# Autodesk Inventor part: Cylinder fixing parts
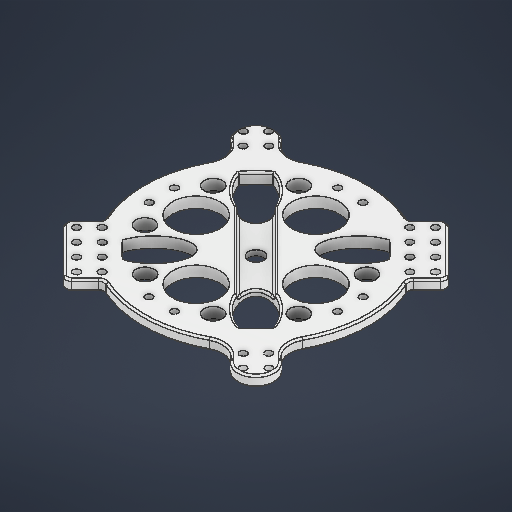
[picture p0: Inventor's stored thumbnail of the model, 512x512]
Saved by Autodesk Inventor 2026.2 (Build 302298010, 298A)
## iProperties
Created: 2026-05
Part Number: Cylinder fixing parts
Material: ABS 플라스틱
Document SubType Name: Modeling
Designer: work
Density: 1.06 g/cm^3
Appearance: 매끄러움 - 흰색
Author: work
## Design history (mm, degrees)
sketch "스케치1"
  geometry: L1 (-15, 60)-(15, 60); L2 (15, 60)-(15, -60); L3 (15, -60)-(-15, -60); L4 (-15, -60)-(-15, 60); L5 (-15, 60)-(15, -60); L6 (15, 60)-(-15, -60); L7 (-7, 52)-(7, 52); L8 (7, 52)-(7, -52); L9 (7, -52)-(-7, -52); L10 (-7, -52)-(-7, 52); L11 (-7, 52)-(7, -52); L12 (7, 52)-(-7, -52); L13 (31, -10)-(0, -10); L14 (0, -10)-(0, 10); L15 (0, 10)-(31, 10); L16 (31, 10)-(31, -10); L17 (25, 5)-(25, -5); L18 (31, 0)-(0, 0); L19 (25, 5)-(15, 5); L20 (15, 5)-(15, -5); L21 (15, -5)-(25, -5); L22 (25, -5)-(25, 5); C1 r 4.25 at (0, 0); C2 r 2 at (7, -52); C3 r 2 at (-7, -52); C4 r 2 at (7, 52); C5 r 2 at (-7, 52); C6 r 2 at (25, 5); C7 r 2 at (25, -5); C8 r 2 at (15, 5); C9 r 2 at (15, -5); 4 further points
  constraints: 44 end point, 9 centre point, 9 coincident, 8 parallel, 7 midpoint, 5 horizontal, 4 perpendicular, 1 point on line, 1 vertical
  dimensions: "d0" = 8.5 diameter of C1; "d1" = 120 distance of L1.end L2.end; "d2" = 30 distance of L1.start L1.end; "d3" = 8 distance between parallel lines of L1 L7; "d4" = 4 diameter of C2; "d5" = 4 diameter of C3; "d6" = 4 diameter of C4; "d7" = 4 diameter of C5; "d8" = 8 distance between parallel lines of L2 L8; "d9" = 16 distance between parallel lines of L2 L16; "d10" = 20 distance of L15.end L13.start; "d11" = 6 distance between parallel lines of L16 L17; "d13" = 4 diameter of C6; "d14" = 4 diameter of C7; "d15" = 10 distance of L17.start L17.end; "d16" = 4 diameter of C8; "d17" = 4 diameter of C9; "d18" = 10 distance between parallel lines of L22 L20
extrude "돌출1" new body sketch "스케치1" distance "d19" = 6; taper "d20" = 0 deg
sketch "스케치2"
  geometry: L1 (30.147, 7)-(-8, 7); L2 (-8, 7)-(-8, -7); L3 (-8, -7)-(30.147, -7); L4 (30.147, -7)-(30.147, 7); L5 (-8, 0)-(30.147, 0); 1 further point
  constraints: 10 end point, 2 midpoint, 2 parallel, 1 horizontal, 1 perpendicular, 1 point on line
  dimensions: "d21" = 8 distance from line of L2 point (0, 0); "d22" = 14 distance between parallel lines of L3 L1
extrude "돌출2" cut sketch "스케치2" distance "d23" = 3; taper "d24" = 0 deg
fillet "모깎기1" dims "d25" = 8
chamfer "모따기1" distance "d26" = 1; stored, may be unused: second distance "d27" = 2, angle "d28" = 45 deg
chamfer "모따기2" distance "d29" = 0.25; stored, may be unused: second distance "d30" = 2, angle "d31" = 45 deg
chamfer "모따기3" distance "d32" = 0.5; stored, may be unused: second distance "d33" = 2, angle "d34" = 45 deg
sketch "스케치3"
  geometry: L1 (-6.5, 24)-(6.5, 24); L2 (6.5, 24)-(6.5, 0); L3 (6.5, 0)-(-6.5, 0); L4 (-6.5, 0)-(-6.5, 24); L5 (-15, -60)-(-15, -15) reference; L6 (15, -60)-(-15, -60) reference; L7 (15, -15)-(15, -60) reference; L8 (60, -15)-(15, -15) reference; L9 (60, 15)-(60, -15) reference; L10 (15, 15)-(60, 15) reference; L11 (15, 60)-(15, 15) reference; L12 (-15, 60)-(15, 60) reference; L13 (-15, 15)-(-15, 60) reference; L14 (-60, 15)-(-15, 15) reference; L15 (-60, -15)-(-60, 15) reference; L16 (-15, -15)-(-60, -15) reference; C1 r 2 at (-52, 7) reference; C2 r 2 at (-52, -7) reference; C3 r 4.25 at (0, 0) reference; C4 r 2 at (52, 7) reference; C5 r 2 at (52, -7) reference; C6 r 2 at (-7, -52) reference; C7 r 2 at (7, -52) reference; C8 r 2 at (-7, 52) reference; C9 r 2 at (7, 52) reference; C10 r 62.5 at (0, 0); 5 further points
  constraints: 8 end point, 3 coincident, 2 parallel, 1 centre point, 1 horizontal, 1 midpoint, 1 perpendicular, 3 other
  dimensions: "d38" = 13 distance between parallel lines of L2 L4; "d39" = 24 distance between parallel lines of L3 L1; "d40" = 125 diameter of C10
extrude "돌출3" join sketch "스케치3" stored distance "d41" = 10; taper "d42" = 0 deg
sketch "스케치4" dims "d44" = 30, "d45" = 5
  geometry: L1 (-52, -7)-(-52, 7); L2 (-46, -7)-(-46, 7); L3 (-58, 7)-(-58, -7); L4 (0, 0)-(-52, 0); L5 (0, 0)-(0, -52); L6 (7, -46)-(-7, -46); L7 (7, -52)-(-7, -52); L8 (-7, -58)-(7, -58); L9 (0, 0)-(52, 0); L10 (46, 7)-(46, -7); L11 (52, 7)-(52, -7); L12 (58, -7)-(58, 7); L13 (0, 0)-(0, 52); L14 (-7, 46)-(7, 46); L15 (-7, 52)-(7, 52); L16 (7, 58)-(-7, 58); L17 (0, 0)-(-44.194, 44.194); L18 (-28.284, 28.284)-(-33, 0); L19 (-28.284, 28.284)-(0, 33); C1 r 4.25 at (0, 0) reference; C2 r 2 at (52, -7) reference; C3 r 2 at (52, 7) reference; C4 r 2 at (-52, 7) reference; C5 r 2 at (-52, -7) reference; C6 r 2 at (-7, 52) reference; C7 r 2 at (7, 52) reference; C8 r 2 at (-7, -52) reference; C9 r 2 at (7, -52) reference; C10 r 13 at (0, -33); C11 r 13 at (33, 0); C12 r 5 at (-42.384, 18.787); C13 r 5 at (-18.787, 42.384); C14 r 5 at (-42.384, -18.787); C15 r 5 at (-18.787, -42.384); C16 r 5 at (18.787, -42.384); C17 r 5 at (42.384, -18.787); C18 r 5 at (42.384, 18.787); C19 r 5 at (18.787, 42.384); A1 r 6 centre (-52, -7) between (-58, -7) and (-46, -7); A2 r 6 centre (-52, 7) between (-46, 7) and (-58, 7); A3 r 6 centre (7, -52) between (7, -58) and (7, -46); A4 r 6 centre (-7, -52) between (-7, -46) and (-7, -58); A5 r 6 centre (52, 7) between (58, 7) and (46, 7); A6 r 6 centre (52, -7) between (46, -7) and (58, -7); A7 r 6 centre (-7, 52) between (-7, 58) and (-7, 46); A8 r 6 centre (7, 52) between (7, 46) and (7, 58); 29 further points
  constraints: 46 end point, 18 centre point, 16 point on circle, 11 point on line, 4 coincident, 4 tangent, 2 vertical, 1 horizontal, 1 midpoint, 1 parallel, 1 symmetric about line, 135 other
  dimensions: "d43" = 12 diameter of A2; "d48" = 360 deg dimension on L4.start L18.end (derived); "d50" = 45 deg angle of L4 L17; "d51" = 40 distance of L18.start point (0, 0); "d52" = 8 distance of point (-16.263, 16.263) point (-10.607, 10.607); "d53" = 5 distance of point (-30.862, 12.823) point (-30.04, 17.755); "d54" = 5 distance of point (-17.755, 30.04) point (-12.823, 30.862); "d55" = 3 dimension on C12; "d56" = 17 distance of L18.start C12.centre; "d57" = 10 diameter of C12; "d60" = 360 deg dimension on L4.start L18.start (derived)
extrude "돌출4" cut sketch "스케치4" distance "d62" = 10; taper "d63" = 0 deg
sketch "스케치5" dims "d68" = 20
  geometry: L1 (0, 0)-(53.033, -53.033); L2 (0, 0)-(62.5, 0); L3 (53.033, -45.962)-(45.962, -53.033); L4 (45.962, -53.033)-(53.033, -60.104); L5 (53.033, -60.104)-(60.104, -53.033); L6 (60.104, -53.033)-(53.033, -45.962); L7 (53.033, -45.962)-(53.033, -60.104); L8 (45.962, -53.033)-(60.104, -53.033); C1 r 2 at (45.962, -53.033); C2 r 2 at (53.033, -60.104); C3 r 2 at (53.033, -45.962); C4 r 2 at (60.104, -53.033); A1 r 62.5 centre (0, 0) between (62.5, 0) and (29.419, -55.143) reference; A2 r 12 centre (35.067, -65.731) between (44.867, -58.805) and (29.419, -55.143); A3 r 12 centre (65.731, -35.067) between (55.143, -29.419) and (58.805, -44.867); 3 further points
  constraints: 16 end point, 6 centre point, 6 point on circle, 5 symmetric about line, 3 coincident, 3 parallel, 2 midpoint, 1 horizontal, 1 perpendicular, 1 tangent, 7 other
  dimensions: "d64" = 45 deg angle of L1 L2; "d65" = 10 distance of L3.start L3.end; "d66" = 10 distance of L4.end L3.end; "d67" = 75 distance of L1.start L1.end; "d69" = 4 diameter of C1; "d70" = 4 diameter of C2; "d71" = 12 radius of A2
extrude "돌출5" join sketch "스케치5" stored distance "d72" = 10; taper "d73" = 0 deg
sketch "스케치6"
  geometry: L1 (26.517, -15.91)-(15.91, -26.517); L2 (15.91, -26.517)-(-26.517, 15.91); L3 (-26.517, 15.91)-(-15.91, 26.517); L4 (-15.91, 26.517)-(26.517, -15.91); L5 (26.517, -15.91)-(-26.517, 15.91); L6 (15.91, -26.517)-(-15.91, 26.517); L7 (26.517, -15.91)-(41.517, -15.91); L8 (5.303, 5.303)-(-5.303, -5.303); 1 further point
  constraints: 16 end point, 4 midpoint, 2 parallel, 1 equal length, 1 horizontal, 1 perpendicular
  dimensions: "d74" = 15 distance of L1.start L1.end; "d75" = 135 deg angle of L1 L7; "d76" = 60 distance of L1.end L2.end
extrude "돌출6" cut sketch "스케치6" distance "d77" = 3; taper "d78" = 0 deg
fillet "모깎기2" dims "d79" = 1
fillet "모깎기3" dims "d80" = 1
sketch "스케치7"
  geometry: L1 (67.175, 38.891)-(-38.891, -67.175); L2 (-38.891, -67.175)-(-67.175, -38.891); L3 (-67.175, -38.891)-(38.891, 67.175); L4 (38.891, 67.175)-(67.175, 38.891); L5 (67.175, 38.891)-(-67.175, -38.891); L6 (-38.891, -67.175)-(38.891, 67.175); L7 (27.008, -14.987)-(-14.987, 27.008) reference; L8 (67.175, 38.891)-(217.175, 38.891); L9 (14.142, -14.142)-(-14.142, 14.142); L10 (0, 0)-(53.033, 53.033); L11 (31.82, 53.033)-(53.033, 31.82); L12 (53.033, 31.82)-(60.104, 38.891); L13 (60.104, 38.891)-(38.891, 60.104); L14 (38.891, 60.104)-(31.82, 53.033); L15 (31.82, 53.033)-(60.104, 38.891); L16 (53.033, 31.82)-(38.891, 60.104); L17 (53.033, 45.962)-(45.962, 38.891); L18 (45.962, 53.033)-(38.891, 45.962); L19 (0, 0)-(-53.033, -53.033); L20 (38.891, 67.175)-(-67.175, -38.891); L21 (-38.891, -67.175)-(38.891, 67.175); L22 (67.175, 38.891)-(-67.175, -38.891); L23 (-38.891, -67.175)-(67.175, 38.891); L24 (-53.033, -45.962)-(-45.962, -38.891); L25 (-53.033, -31.82)-(-31.82, -53.033); L26 (-53.033, -31.82)-(-38.891, -60.104); L27 (-31.82, -53.033)-(-60.104, -38.891); L28 (-38.891, -60.104)-(-60.104, -38.891); L29 (-67.175, -38.891)-(-38.891, -67.175); L30 (-38.891, -67.175)-(-38.891, -217.175); L31 (-31.82, -53.033)-(-38.891, -60.104); L32 (-45.962, -53.033)-(-38.891, -45.962); L33 (-60.104, -38.891)-(-53.033, -31.82); L34 (-27.008, 14.987)-(14.987, -27.008) reference; L35 (27.008, -14.987)-(-14.987, 27.008) reference; C1 r 4.25 at (0, 0) reference; C2 r 2 at (53.033, 31.82); C3 r 2 at (60.104, 38.891); C4 r 2 at (53.033, 45.962); C5 r 2 at (45.962, 38.891); C6 r 2 at (38.891, 45.962); C7 r 2 at (45.962, 53.033); C8 r 2 at (38.891, 60.104); C9 r 2 at (31.82, 53.033); C10 r 2 at (-53.033, -31.82); C11 r 2 at (-53.033, -45.962); C12 r 2 at (-60.104, -38.891); C13 r 2 at (-45.962, -38.891); C14 r 2 at (-45.962, -53.033); C15 r 2 at (-38.891, -45.962); C16 r 2 at (-31.82, -53.033); C17 r 2 at (-38.891, -60.104); C18 r 2 at (7, -52) reference; C19 r 2 at (-7, -52) reference; C20 r 2 at (7, 52) reference; C21 r 2 at (-7, 52) reference; C22 r 2 at (-52, -7) reference; C23 r 2 at (-52, 7) reference; C24 r 2 at (52, 7) reference; C25 r 2 at (52, -7) reference; C26 r 5 at (-42.384, 18.787) reference; C27 r 5 at (-18.787, 42.384) reference; C28 r 5 at (-42.384, -18.787) reference; C29 r 5 at (18.787, -42.384) reference; C30 r 5 at (42.384, 18.787) reference; C31 r 5 at (42.384, -18.787) reference; C32 r 5 at (-18.787, -42.384) reference; C33 r 13 at (0, 33) reference; C34 r 13 at (-33, 0) reference; C35 r 13 at (0, -33) reference; C36 r 13 at (33, 0) reference; C37 r 2 at (60.104, -53.033) reference; C38 r 2 at (53.033, -45.962) reference; C39 r 2 at (53.033, -60.104) reference; C40 r 2 at (45.962, -53.033) reference; A1 r 62.5 centre (0, 0) between (55.143, -29.419) and (29.419, -55.143) reference; A2 r 12 centre (35.067, -65.731) between (44.867, -58.805) and (29.419, -55.143) reference; A3 r 10 centre (53.033, -53.033) between (44.867, -58.805) and (58.805, -44.867) reference; A4 r 12 centre (65.731, -35.067) between (55.143, -29.419) and (58.805, -44.867) reference; A5 r 52.469 centre (0, 0) between (41.46, 32.157) and (32.157, 41.46) reference; A6 r 53.469 centre (0, 0) between (32.373, -42.555) and (42.555, -32.373) reference; A7 r 53.469 centre (0, 0) between (-32.373, 42.555) and (-42.555, 32.373) reference; A8 r 52.469 centre (0, 0) between (-41.46, -32.157) and (-32.157, -41.46) reference; 17 further points; 2 other entities
  constraints: 64 end point, 29 symmetric about line, 16 centre point, 12 coincident, 9 midpoint, 6 perpendicular, 6 point on line, 4 parallel, 1 equal length, 1 horizontal, 18 other
  dimensions: "d81" = 150 distance of L1.start L1.end; "d82" = 135 deg angle of L1 L8 (derived); "d83" = 40 distance of L1.end L2.end; "d84" = 30 distance of L12.end L13.end; "d85" = 10 distance of L13.end L11.start; "d86" = 4 diameter of C2; "d87" = 10 distance between parallel lines of L17 L12; "d88" = 4 diameter of C3; "d89" = 4 diameter of C4; "d90" = 4 diameter of C5; "d91" = 5 distance from line of L4 L17.start
  node "투영된 루프3"
extrude "돌출7" join sketch "스케치7" stored distance "d92" = 3; taper "d93" = 0 deg
extrude "돌출8" cut sketch "스케치7" extent not by distance; stored distance "d94" = 10; taper "d95" = 0 deg
fillet "모깎기4" dims "d96" = 3
node "작업 평면1"
node "작업 평면2"
chamfer "모따기4" distance "d97" = 1; stored, may be unused: second distance "d98" = 2, angle "d99" = 45 deg
node "솔리드1"
pattern_circular "원형 패턴1" dims angle "d36" = 360 deg
mirror "미러1"
node "투영된 루프1"
node "투영된 루프2"
node "스케치 - 원형 패턴1" dims "d48" = 360 deg (derived)
node "스케치 - 원형 패턴2" dims "d60" = 360 deg (derived)
